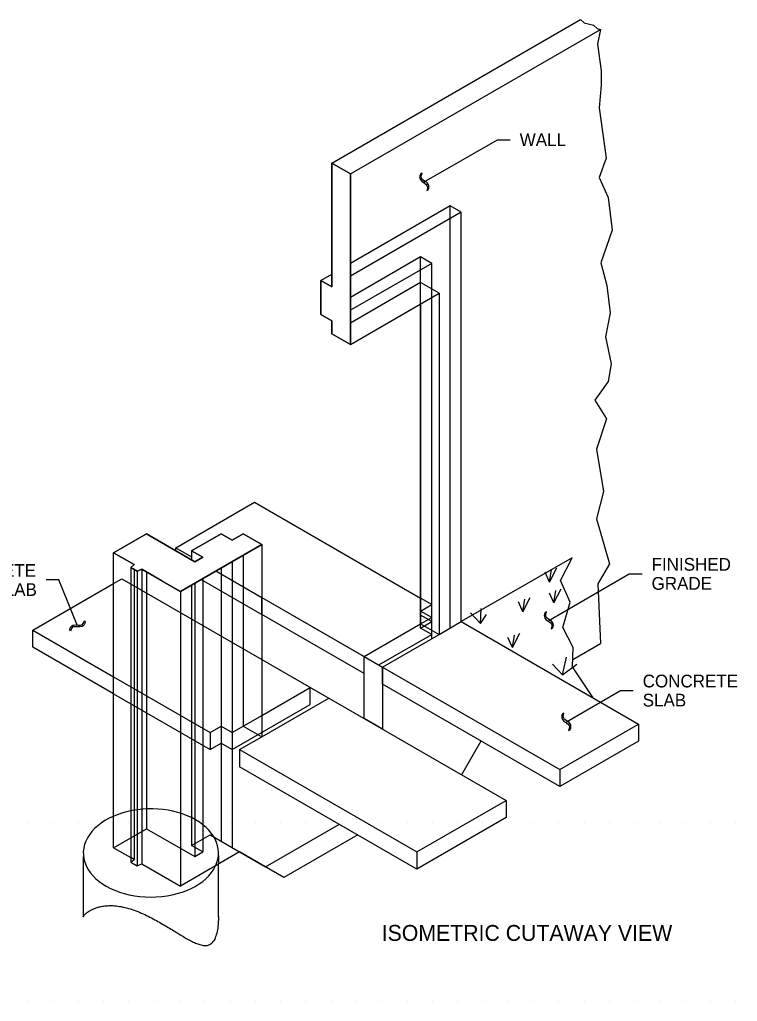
# Model space of a CAD drawing. Extents: x 99862 to 103151, y 100000 to 102076.
# Drawn here: x 101581 to 102484, y 100000 to 101235 of the extents above; entities that cross this region are included whole.
import ezdxf

# ---------------------------------------------------------------- set-up
doc = ezdxf.new("R2010")
doc.units = 0
for name, color, linetype in [('Level 1', 7, 'Continuous'), ('Level 15', 7, 'Continuous'), ('Level 16', 7, 'Continuous'), ('Level 17', 7, 'Continuous'), ('Level 20', 7, 'Continuous'), ('Level 8', 7, 'Continuous')]:
    doc.layers.add(name, color=color, linetype=linetype)

msp = doc.modelspace()

# ---------------------------------------------------------------- linework, layer by layer
at = {"layer": 'Level 1'}
for p, q in [((101590.9, 100225), (101590.9, 100225)), ((101622.7, 100225), (101622.7, 100225)), ((101654.5, 100225), (101654.5, 100225)), ((101686.4, 100225), (101686.4, 100225)), ((101718.2, 100225), (101718.2, 100225)), ((101750, 100225), (101750, 100225)), ((101781.8, 100225), (101781.8, 100225)), ((101813.6, 100225), (101813.6, 100225)), ((101845.5, 100225), (101845.5, 100225)), ((101877.3, 100225), (101877.3, 100225)), ((101909.1, 100225), (101909.1, 100225)), ((101940.9, 100225), (101940.9, 100225)), ((101972.7, 100225), (101972.7, 100225)), ((102004.5, 100225), (102004.5, 100225)), ((102036.4, 100225), (102036.4, 100225)), ((102068.2, 100225), (102068.2, 100225)), ((102100, 100225), (102100, 100225)), ((102131.8, 100225), (102131.8, 100225)), ((102163.6, 100225), (102163.6, 100225)), ((102195.5, 100225), (102195.5, 100225)), ((102227.3, 100225), (102227.3, 100225)), ((102259.1, 100225), (102259.1, 100225)), ((102290.9, 100225), (102290.9, 100225)), ((102322.7, 100225), (102322.7, 100225)), ((102354.5, 100225), (102354.5, 100225)), ((102386.4, 100225), (102386.4, 100225)), ((102418.2, 100225), (102418.2, 100225)), ((102450, 100225), (102450, 100225)), ((102481.8, 100225), (102481.8, 100225)), ((101590.9, 100000), (101590.9, 100000)), ((101622.7, 100000), (101622.7, 100000)), ((101654.5, 100000), (101654.5, 100000)), ((101686.4, 100000), (101686.4, 100000)), ((101718.2, 100000), (101718.2, 100000)), ((101750, 100000), (101750, 100000)), ((101781.8, 100000), (101781.8, 100000)), ((101813.6, 100000), (101813.6, 100000)), ((101845.5, 100000), (101845.5, 100000)), ((101877.3, 100000), (101877.3, 100000)), ((101909.1, 100000), (101909.1, 100000)), ((101940.9, 100000), (101940.9, 100000)), ((101972.7, 100000), (101972.7, 100000)), ((102004.5, 100000), (102004.5, 100000)), ((102036.4, 100000), (102036.4, 100000)), ((102068.2, 100000), (102068.2, 100000)), ((102100, 100000), (102100, 100000)), ((102131.8, 100000), (102131.8, 100000)), ((102163.6, 100000), (102163.6, 100000)), ((102195.5, 100000), (102195.5, 100000)), ((102227.3, 100000), (102227.3, 100000)), ((102259.1, 100000), (102259.1, 100000)), ((102290.9, 100000), (102290.9, 100000)), ((102322.7, 100000), (102322.7, 100000)), ((102354.5, 100000), (102354.5, 100000)), ((102386.4, 100000), (102386.4, 100000)), ((102418.2, 100000), (102418.2, 100000)), ((102450, 100000), (102450, 100000)), ((102481.8, 100000), (102481.8, 100000))]:
    msp.add_line(p, q, dxfattribs=at)
at = {"layer": 'Level 15'}
for p, q in [((102089.8, 101030.7), (102181.8, 101083.8)), ((102181.8, 101083.8), (102197.8, 101083.8)), ((101630, 100530), (101614, 100530)), ((101653.5, 100472.2), (101630, 100530)), ((102246.4, 100479.2), (102347.7, 100537.7)), ((102347.7, 100537.7), (102363.7, 100537.7)), ((102268.5, 100351.7), (102336.5, 100390.9)), ((102336.5, 100390.9), (102352.5, 100390.9))]:
    msp.add_line(p, q, dxfattribs=at)
at = {"layer": 'Level 16'}
for points in [[(101973.6, 101054.3), (101996.9, 101040.9), (101996.9, 100826.3), (101973.6, 100839.7), (101973.6, 100855.8), (101959.7, 100863.8), (101959.7, 100906.7), (101973.6, 100898.7)], [(101759.7, 100529), (101734.6, 100543.5), (101728.7, 100541.2), (101720.7, 100545.8), (101724.6, 100549.3), (101699, 100564), (101740.4, 100587.9), (101801.1, 100552.9), (101811, 100558.6), (101797.1, 100566.6), (101834.3, 100588.1), (101848.2, 100580), (101862.1, 100588.1), (101885.4, 100574.7), (101783, 100515.6)], [(101885.4, 100486.6), (101885.4, 100508.1), (102260.3, 100291.7), (102260.3, 100270.2), (102037.2, 100398.9), (102037.2, 100342.4), (102014, 100355.8), (102014, 100412.4)]]:
    msp.add_lwpolyline(points, close=True, dxfattribs=at)
at = {"layer": 'Level 17'}
for p, q in [((101996.9, 101040.9), (102311.5, 101222.5)), ((102122.3, 100469.5), (102122.3, 101000.6)), ((102136.2, 100477.6), (102136.2, 100992.6)), ((102085.1, 100469.5), (102085.1, 100936.3)), ((102099.1, 100456.1), (102099.1, 100928.2)), ((101996.9, 100826.3), (102108.4, 100890.7)), ((102108.4, 100890.7), (102108.4, 100461.5)), ((102085.1, 100877.2), (102085.1, 100474.9)), ((101777.1, 100570.6), (101876.1, 100627.8)), ((101876.1, 100627.8), (102085.1, 100507.1)), ((101797.1, 100566.6), (101797.1, 100555.2)), ((101885.4, 100574.7), (101885.4, 100332.7)), ((101848.2, 100553.2), (101848.2, 100193.2)), ((101720.7, 100545.8), (101728.7, 100541.2)), ((101720.7, 100545.8), (101720.7, 100175.1)), ((101724.6, 100543.6), (101724.6, 100178.5)), ((101728.7, 100541.2), (101728.7, 100170.5)), ((101734.6, 100543.5), (101734.6, 100172.8)), ((101740.4, 100540.1), (101740.4, 100217.2)), ((101834.3, 100545.2), (101834.3, 100201.3)), ((101811, 100531.8), (101811, 100187.9)), ((101597.3, 100466.8), (101699, 100525.5)), ((101783, 100515.6), (101783, 100144.8)), ((101797.1, 100523.7), (101797.1, 100195.9)), ((101801.1, 100526), (101801.1, 100182.1)), ((102108.4, 100461.5), (102136.2, 100477.6)), ((102136.2, 100477.6), (102359.3, 100348.8)), ((101597.3, 100466.8), (101699, 100408.1)), ((102014, 100433.8), (102085.1, 100474.9)), ((102085.1, 100474.9), (102108.4, 100461.5)), ((102037.2, 100420.4), (102108.4, 100461.5)), ((102276.6, 100429.8), (102311.5, 100450)), ((101885.4, 100430.1), (102192.7, 100252.6)), ((101885.4, 100359.5), (101946.4, 100394.8)), ((101885.4, 100332.7), (101969.7, 100381.4)), ((102260.3, 100291.7), (102359.3, 100348.8)), ((101857.5, 100316.6), (101885.4, 100332.7)), ((101857.5, 100316.6), (102080.5, 100187.9)), ((101857.5, 100316.6), (101857.5, 100295.2)), ((102080.5, 100187.9), (102192.7, 100252.6)), ((102192.7, 100252.6), (102192.7, 100231.2)), ((101830.8, 100183.5), (101830.8, 100172.5)), ((102080.5, 100187.9), (102080.5, 100166.4))]:
    msp.add_line(p, q, dxfattribs=at)
for points in [[(101973.6, 101054.3), (102286.3, 101234.8)], [(102286.3, 101234.8), (102290.7, 101230.7), (102302.7, 101227.9), (102307.1, 101223.5), (102311.5, 101222.5), (102307.7, 101203.8), (102312.2, 101170.6), (102312.2, 101152.4), (102309.9, 101123.7), (102318.6, 101060.5), (102309.9, 101036.4), (102320.9, 101010.9), (102326.3, 100969.9), (102311.8, 100929), (102319.5, 100900.5), (102323.6, 100866), (102317.7, 100835.9), (102325, 100801.8), (102320.9, 100779.5), (102304.5, 100756.3), (102319, 100732.6), (102306.3, 100694.4), (102315.4, 100641.5), (102306.3, 100607.1), (102322.7, 100550.5), (102308.1, 100525.1), (102311.5, 100450)], [(101996.9, 101040.9), (101973.6, 101054.3), (101973.6, 100898.7), (101959.7, 100906.7), (101959.7, 100863.8), (101973.6, 100855.8), (101973.6, 100839.7), (101996.9, 100826.3), (101996.9, 101040.9)], [(102122.3, 101000.6), (101996.9, 100928.2)], [(102136.2, 100992.6), (102122.3, 101000.6)], [(102136.2, 100992.6), (101996.9, 100912.1)], [(102085.1, 100936.3), (101996.9, 100885.3)], [(102099.1, 100928.2), (102085.1, 100936.3)], [(102099.1, 100928.2), (101996.9, 100869.2)], [(101959.7, 100906.7), (101973.6, 100914.8)], [(102085.1, 100904.1), (101996.9, 100853.1)], [(102108.4, 100890.7), (102085.1, 100904.1)], [(101862.1, 100588.1), (101848.2, 100580), (101834.3, 100588.1), (101797.1, 100566.6), (101811, 100558.6), (101801.1, 100552.9), (101740.4, 100587.9), (101699, 100564), (101724.6, 100549.3), (101720.7, 100545.8), (101728.7, 100541.2), (101734.6, 100543.5), (101783, 100515.6), (101885.4, 100574.7), (101862.1, 100588.1)], [(101699, 100193.3), (101699, 100564)], [(101777.1, 100566.7), (101777.1, 100570.6), (101797.1, 100559.1)], [(101862.1, 100561.3), (101862.1, 100346.1)], [(101827.7, 100541.4), (101885.4, 100508.1)], [(101699, 100525.5), (101709.4, 100531.5)], [(101709.4, 100531.5), (101885.4, 100429.9)], [(101809.1, 100530.7), (101885.4, 100486.6)], [(101885.4, 100508.1), (102014, 100433.8)], [(102085.1, 100474.9), (102099.1, 100482.9), (102085.1, 100491), (102099.1, 100499), (102085.1, 100507.1)], [(102014, 100412.4), (101885.4, 100486.6)], [(102032.6, 100423.1), (102099.1, 100461.5), (102085.1, 100469.5), (102099.1, 100477.6), (102085.1, 100485.6)], [(101699, 100386.7), (101597.3, 100445.4), (101597.3, 100466.8)], [(102014, 100355.8), (102014, 100433.8), (102037.2, 100420.4), (102037.2, 100342.4)], [(102260.3, 100291.7), (102260.3, 100270.2), (102037.2, 100398.9), (102037.2, 100420.4), (102260.3, 100291.7)], [(101699, 100408.1), (101820.3, 100338.1)], [(101820.3, 100316.6), (101834.3, 100324.7), (101848.2, 100316.6), (101946.4, 100373.3), (101946.4, 100394.8)], [(101699, 100386.7), (101820.3, 100316.6)], [(101820.3, 100338.1), (101834.3, 100346.1), (101848.2, 100338.1), (101885.4, 100359.5)], [(101862.1, 100346.1), (101885.4, 100332.7)], [(102359.3, 100348.8), (102359.3, 100327.4), (102260.3, 100270.2)], [(101820.3, 100338.1), (101820.3, 100316.6)], [(102161.1, 100327.4), (102136.6, 100285)], [(102192.7, 100231.2), (102080.5, 100166.4), (101857.5, 100295.2)], [(101801.1, 100182.1), (101811, 100187.9), (101797.1, 100195.9), (101820.3, 100209.6), (101890, 100169.1), (101982.9, 100222.7)], [(101699, 100193.3), (101740.4, 100217.2)], [(101740.4, 100217.2), (101801.1, 100182.1)], [(102006.2, 100209.3), (101913.2, 100155.7), (101857.5, 100187.9), (101783, 100144.8)], [(101699, 100193.3), (101720.7, 100180.8)], [(101660.9, 100106.4), (101660.9, 100182.2)], [(101720.7, 100175.1), (101724.6, 100178.5), (101720.7, 100180.8)], [(101720.7, 100175.1), (101728.7, 100170.5), (101734.6, 100172.8)], [(101734.6, 100172.8), (101783, 100144.8)], [(101830.8, 100106.2), (101830.8, 100172.5)]]:
    msp.add_lwpolyline(points, dxfattribs=at)
for start_param, end_param in [(5.987372, 8.437385), (2.154199, 5.987372)]:
    msp.add_ellipse((101745.9, 100186.6), major_axis=(85.1, 0), ratio=0.652174, start_param=start_param, end_param=end_param, dxfattribs=at)
for points in [[(101661, 100106.4), (101660.8, 100106.4), (101660.7, 100106.7), (101661.2, 100107.6), (101662.2, 100108.9), (101663.8, 100110.5), (101666.1, 100112.1), (101668.7, 100113.9), (101672, 100115.7), (101676, 100117.4), (101680.6, 100118.8), (101686.2, 100119.9), (101692.6, 100120.6), (101700.1, 100120.4), (101708.5, 100119.3), (101717.6, 100117.1), (101727, 100114), (101736.1, 100110.1), (101744.7, 100106), (101752.8, 100101.6), (101760.5, 100097.3), (101767.7, 100092.9), (101774.6, 100088.7), (101781.2, 100084.7), (101787.4, 100080.9), (101793.4, 100077.5), (101799.2, 100074.6), (101804.8, 100072.1), (101810.2, 100070.5), (101815.3, 100070), (101820.2, 100071), (101822.9, 100073.6), (101824.3, 100075.3)], [(101830.8, 100106.6), (101830.8, 100104.1), (101830.6, 100098.5), (101829.7, 100090), (101827.7, 100081.6), (101825.6, 100077.3), (101824.3, 100075.3)]]:
    msp.add_open_spline(points, degree=3, dxfattribs=at)
at = {"layer": 'Level 20'}
for p, q in [((102084.3, 101038.7), (102084, 101036.9)), ((102084, 101036.9), (102084.2, 101035.2)), ((102084.2, 101035.2), (102084.8, 101033.6)), ((102085, 101040.5), (102084.3, 101038.7)), ((102084.8, 101033.6), (102086.6, 101031.5)), ((102086.9, 101041.5), (102085, 101040.5)), ((102085.8, 101037.5), (102086.1, 101039.2)), ((102086, 101036.2), (102085.8, 101037.5)), ((102086.5, 101034.9), (102086, 101036.2)), ((102086.1, 101039.2), (102086.9, 101041.5)), ((102087.7, 101033.5), (102086.5, 101034.9)), ((102089.8, 101032), (102087.7, 101033.5)), ((102086.6, 101031.5), (102090.2, 101029)), ((102093.2, 101029.7), (102089.8, 101032)), ((102090.2, 101029), (102092.2, 101027.6)), ((102092.2, 101027.6), (102093.1, 101026.4)), ((102093.7, 101023.4), (102092.8, 101019.9)), ((102092.8, 101019.9), (102094.6, 101020.9)), ((102093.1, 101026.4), (102093.6, 101025.1)), ((102094.8, 101027.8), (102093.2, 101029.7)), ((102093.6, 101025.1), (102093.7, 101023.4)), ((102094.6, 101020.9), (102095.3, 101022.9)), ((102095.4, 101026.3), (102094.8, 101027.8)), ((102095.3, 101022.9), (102095.6, 101024.7)), ((102095.6, 101024.7), (102095.4, 101026.3)), ((102243.5, 100490.1), (102241.7, 100489)), ((102242.8, 100487.7), (102243.5, 100490.1)), ((101661.6, 100476.7), (101662.5, 100479)), ((101662.5, 100479), (101663.3, 100477)), ((102240.9, 100487.2), (102240.6, 100485.4)), ((102240.6, 100485.4), (102240.8, 100483.7)), ((102240.8, 100483.7), (102241.5, 100482.1)), ((102241.7, 100489), (102240.9, 100487.2)), ((102241.5, 100482.1), (102243.2, 100480)), ((102242.5, 100486), (102242.8, 100487.7)), ((102242.6, 100484.7), (102242.5, 100486)), ((102243.1, 100483.4), (102242.6, 100484.7)), ((102244.4, 100482), (102243.1, 100483.4)), ((102243.2, 100480), (102246.9, 100477.5)), ((102246.5, 100480.5), (102244.4, 100482)), ((102249.9, 100478.2), (102246.5, 100480.5)), ((102246.9, 100477.5), (102248.9, 100476.1)), ((102251.4, 100476.3), (102249.9, 100478.2)), ((101643.7, 100467.4), (101644.3, 100469.5)), ((101644.5, 100465.5), (101643.7, 100467.4)), ((101644.3, 100469.5), (101645.2, 100471)), ((101646, 100468.9), (101644.5, 100465.5)), ((101645.2, 100471), (101646.3, 100472.2)), ((101647, 100470.1), (101646, 100468.9)), ((101646.3, 100472.2), (101647.8, 100473)), ((101648.2, 100470.9), (101647, 100470.1)), ((101647.8, 100473), (101650.2, 100473.6)), ((101649.7, 100471.2), (101648.2, 100470.9)), ((101652.1, 100471.1), (101649.7, 100471.2)), ((101650.2, 100473.6), (101654.3, 100473.3)), ((101656.5, 100470.9), (101652.1, 100471.1)), ((101654.3, 100473.3), (101656.8, 100473.1)), ((101659.2, 100471.4), (101656.5, 100470.9)), ((101656.8, 100473.1), (101658.7, 100473.5)), ((101658.7, 100473.5), (101659.8, 100474.2)), ((101660.7, 100472.3), (101659.2, 100471.4)), ((101659.8, 100474.2), (101660.8, 100475.2)), ((101661.9, 100473.5), (101660.7, 100472.3)), ((101660.8, 100475.2), (101661.6, 100476.7)), ((101662.7, 100475.1), (101661.9, 100473.5)), ((101663.3, 100477), (101662.7, 100475.1)), ((102248.9, 100476.1), (102249.8, 100474.9)), ((102250.3, 100471.9), (102249.4, 100468.4)), ((102249.4, 100468.4), (102251.2, 100469.4)), ((102249.8, 100474.9), (102250.3, 100473.6)), ((102250.3, 100473.6), (102250.3, 100471.9)), ((102251.2, 100469.4), (102252, 100471.4)), ((102252.1, 100474.8), (102251.4, 100476.3)), ((102252, 100471.4), (102252.3, 100473.2)), ((102252.3, 100473.2), (102252.1, 100474.8)), ((102262.9, 100359.6), (102262.7, 100357.9)), ((102262.7, 100357.9), (102262.9, 100356.2)), ((102263.7, 100361.5), (102262.9, 100359.6)), ((102262.9, 100356.2), (102263.5, 100354.5)), ((102263.5, 100354.5), (102265.3, 100352.5)), ((102265.5, 100362.5), (102263.7, 100361.5)), ((102264.5, 100358.5), (102264.8, 100360.2)), ((102264.7, 100357.1), (102264.5, 100358.5)), ((102265.2, 100355.9), (102264.7, 100357.1)), ((102264.8, 100360.2), (102265.5, 100362.5)), ((102266.4, 100354.5), (102265.2, 100355.9)), ((102268.5, 100353), (102266.4, 100354.5)), ((102265.3, 100352.5), (102268.9, 100349.9)), ((102271.9, 100350.7), (102268.5, 100353)), ((102268.9, 100349.9), (102270.9, 100348.5)), ((102270.9, 100348.5), (102271.8, 100347.4)), ((102272.4, 100344.4), (102271.4, 100340.8)), ((102271.4, 100340.8), (102273.3, 100341.9)), ((102271.8, 100347.4), (102272.3, 100346)), ((102273.5, 100348.8), (102271.9, 100350.7)), ((102272.3, 100346), (102272.4, 100344.4)), ((102273.3, 100341.9), (102274, 100343.9)), ((102274.1, 100347.3), (102273.5, 100348.8)), ((102274, 100343.9), (102274.3, 100345.7)), ((102274.3, 100345.7), (102274.1, 100347.3))]:
    msp.add_line(p, q, dxfattribs=at)
at = {"layer": 'Level 8'}
for p, q in [((102247.4, 100527.4), (102241.7, 100540)), ((102247.4, 100527.4), (102256.6, 100545.4)), ((102247.4, 100527.4), (102249.8, 100543.2)), ((102252.8, 100501.1), (102262, 100519)), ((102252.8, 100501.1), (102255.3, 100516.8)), ((102213.7, 100490.1), (102208.1, 100502.7)), ((102213.7, 100490.1), (102222.9, 100508.1)), ((102213.7, 100490.1), (102216.2, 100505.9)), ((102252.8, 100501.1), (102247.2, 100513.6)), ((102160.6, 100475.1), (102161.3, 100494)), ((102160.6, 100475.1), (102148.1, 100488.6)), ((102160.6, 100475.1), (102168.1, 100486.8)), ((102200.7, 100445), (102195, 100457.6)), ((102200.7, 100445), (102209.9, 100463)), ((102200.7, 100445), (102203.1, 100460.7)), ((102263.6, 100410.8), (102268.8, 100432.8)), ((102263.6, 100410.8), (102251, 100424.3)), ((102263.6, 100410.8), (102281.6, 100424.3))]:
    msp.add_line(p, q, dxfattribs=at)
msp.add_lwpolyline([(102302.1, 100381.8), (102276.2, 100420.6), (102277.2, 100445), (102264, 100470.2), (102273.1, 100502.1), (102261.3, 100529.4), (102275.6, 100558), (102136.2, 100477.6)], dxfattribs=at)

# ---------------------------------------------------------------- texts
at = {"layer": 'Level 20'}
for s, height, p in [('WALL', 16, (102209.8, 101075.8)), ('FINISHED', 16, (102375.7, 100541.7)), ('GRADE', 16, (102375.7, 100517.7)), ('CONCRETE', 16, (102364.5, 100394.9)), ('SLAB', 16, (102364.5, 100370.9)), ('ISOMETRIC CUTAWAY VIEW', 20, (102036.2, 100076.1))]:
    msp.add_text(s, height=height, dxfattribs=at).set_placement(p)
for s, p in [('CONCRETE', (101481.3, 100534)), ('SLAB', (101547.7, 100510))]:
    msp.add_text(s, height=16, rotation=360, dxfattribs=at).set_placement(p)

doc.saveas('drawing.dxf')
